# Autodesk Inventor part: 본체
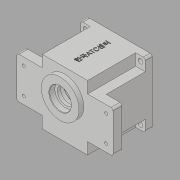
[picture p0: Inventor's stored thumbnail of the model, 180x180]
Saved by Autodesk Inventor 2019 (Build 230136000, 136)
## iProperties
Created: 2020-01
Part Number: 본체
Material: 일반
Document SubType Name: Modeling
Designer: 323-10
Density: 1 g/cm^3
Appearance: 기본값
Mass: 876.342 g
Surface Area: 793.825 cm^2
Volume: 324.571 cm^3
Author: 323-10
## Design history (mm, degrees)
sketch "스케치1"
  geometry: L1 (-47, -47)-(47, -47); L2 (47, -47)-(47, 47); L3 (47, 47)-(-47, 47); L4 (-47, 47)-(-47, -47); L5 (-47, -47)-(47, 47); L6 (47, -47)-(-47, 47); 1 further point
  constraints: 12 end point, 2 midpoint, 2 parallel, 1 horizontal, 1 perpendicular
  dimensions: "d0" = 94 distance of L3.end L2.end; "d1" = 94 distance of L2.end L1.end
extrude "돌출1" new body sketch "스케치1" distance "d2" = 80; taper "d3" = 0 deg
sketch "스케치2"
  geometry: L1 (70, -30)-(-70, -30); L2 (-70, -30)-(-70, 30); L3 (-70, 30)-(70, 30); L4 (70, 30)-(70, -30); L5 (70, -30)-(-70, 30); L6 (-70, -30)-(70, 30); 1 further point
  constraints: 12 end point, 2 midpoint, 2 parallel, 1 horizontal, 1 perpendicular
  dimensions: "d4" = 140 distance of L2.end L3.end; "d5" = 60 distance of L1.end L2.end
extrude "돌출2" join sketch "스케치2" distance "d6" = 13; taper "d7" = 0 deg
sketch "스케치3"
  geometry: C1 r 27.5 at (0, 11); 1 further point
  constraints: 1 centre point, 1 vertical alignment
  dimensions: "d8" = 55 diameter of C1; "d9" = 11 distance of point (0, 0) C1.centre
extrude "돌출3" join sketch "스케치3" distance "d10" = 7; taper "d11" = 0 deg
sketch "스케치4"
  geometry: C1 r 27.5 at (0, 0) reference; C2 r 16 at (0, 0); 1 further point
  constraints: 1 centre point, 1 coincident
  dimensions: "d12" = 32 diameter of C2
extrude "돌출4" cut sketch "스케치4" distance "d13" = 8.3; taper "d14" = 0 deg
sketch "스케치5"
  geometry: C1 r 40 at (0, 0); 1 further point
  constraints: 1 centre point, 1 coincident
  dimensions: "d15" = 80 diameter of C1
extrude "돌출5" cut sketch "스케치5" distance "d16" = 71; taper "d17" = 0 deg
sketch "스케치6"
  geometry: C1 r 21 at (0, 11); C2 r 15 at (0, -20); 1 further point
  constraints: 2 centre point, 2 vertical alignment
  dimensions: "d18" = 11 distance of point (0, 0) C1.centre; "d20" = 20 distance of C2.centre point (0, 0); "d21" = 21 radius of C1; "d22" = 15 radius of C2
extrude "돌출6" join sketch "스케치6" distance "d23" = 7; taper "d24" = 0 deg
sketch "스케치7"
  geometry: C1 r 17.5 at (0, 11); A1 r 21 centre (0, 11) between (8.978, -7.984) and (-8.978, -7.984) reference; 1 further point
  constraints: 1 centre point, 1 coincident
  dimensions: "d25" = 35 diameter of C1
extrude "돌출7" cut sketch "스케치7" distance "d26" = 10; taper "d27" = 0 deg
sketch "스케치8"
  geometry: C1 r 11 at (0, -20); A1 r 15 centre (0, -20) between (-8.978, -7.984) and (8.978, -7.984) reference; 1 further point
  constraints: 1 centre point, 1 coincident
  dimensions: "d28" = 22 diameter of C1
extrude "돌출8" cut sketch "스케치8" distance "d29" = 7; taper "d30" = 0 deg
sketch "스케치9"
  geometry: C1 r 11 at (0, 0) reference; C2 r 9.5 at (0, 0); 1 further point
  constraints: 1 centre point, 1 coincident
  dimensions: "d31" = 19 diameter of C2
extrude "돌출9" cut sketch "스케치9" distance "d32" = 3; taper "d33" = 0 deg
sketch "스케치10"
  geometry: C1 r 16 at (0, 0) reference; C2 r 12.5 at (0, 0); 1 further point
  constraints: 1 centre point, 1 coincident
  dimensions: "d34" = 25 diameter of C2
extrude "돌출10" cut sketch "스케치10" extent not by distance; stored distance "d35" = 3; taper "d36" = 0 deg
sketch "스케치11"
  geometry: C1 r 43 at (0, 0); 1 further point
  constraints: 1 centre point, 1 coincident
  dimensions: "d37" = 86 diameter of C1
extrude "돌출11" cut sketch "스케치11" distance "d38" = 9; taper "d39" = 0 deg
sketch "스케치12" dims "d40" = 36
  geometry: L1 (36, -4)-(39.799, -4); L2 (36, 4)-(39.799, 4); A1 r 4 centre (36, 0) between (36, 4) and (36, -4); A2 r 40 centre (0, 0) between (39.799, -4) and (39.799, 4) reference; A3 r 40 centre (0, 0) between (39.799, -4) and (39.799, 4); A4 r 4 centre (36, 0) between (40, 0) and (36, 4); A5 r 4 centre (36, 0) between (36, -4) and (40, 0); 2 further points
  constraints: 11 point on circle, 4 centre point, 4 end point, 4 tangent, 2 coincident, 2 horizontal, 2 horizontal alignment, 2 other
  dimensions: "d42" = 4 radius of A4
extrude "돌출12" join sketch "스케치12" stored distance "d43" = 9; taper "d44" = 0 deg
fillet "모깎기1" dims "d45" = 3
sketch "스케치13"
  geometry: 2 further points
  dimensions: "d46" = 19 vertical distance of point (0, 0) point (-60, 19); "d47" = 60 horizontal distance of point (0, 0) point (-60, 19)
hole "구멍1" sketch "스케치13" at (-60, 19) diameter "d48" = 4.5; stored, may be unused: countersink angle "d52" = 90 deg, drill point angle "d54" = 118 deg; dims "d49" = 6, "d50" = 10, "d51" = 5, "d53" = 8
sketch "스케치14"
  geometry: L1 (47, 30)-(47, 47) reference; L2 (47, 47)-(33, 47); L3 (33, 47)-(33, 30); L4 (33, 30)-(47, 30); L5 (47, 30)-(47, 47); 1 further point
  constraints: 8 end point, 2 parallel, 1 horizontal, 1 perpendicular
  dimensions: "d55" = 33 distance from line of point (0, 0) L3; "d56" = 30 distance from line of point (0, 0) L4
extrude "돌출13" cut sketch "스케치14" distance "d57" = 70; taper "d58" = 0 deg
sketch "스케치15"
  geometry: C1 r 3.5 at (40, 40); 1 further point
  constraints: 1 centre point
  dimensions: "d59" = 7 diameter of C1; "d60" = 40 horizontal distance of point (0, 0) C1.centre; "d61" = 40 horizontal distance of point (0, 0) C1.centre
extrude "돌출14" cut sketch "스케치15" extent not by distance; stored distance "d62" = 70; taper "d63" = 0 deg
chamfer "모따기1" distance "d64" = 0.8; stored, may be unused: second distance "d65" = 2, angle "d66" = 30 deg
chamfer "모따기2" distance "d67" = 1; stored, may be unused: second distance "d68" = 2, angle "d69" = 45 deg
fillet "모깎기2" dims "d70" = 3
chamfer "모따기3" distance "d71" = 1; stored, may be unused: second distance "d72" = 2, angle "d73" = 45 deg
sketch "스케치16"
  geometry: A1 r 4 centre (36, 0) between (36, 4) and (36, -4) reference; 2 further points
  constraints: 1 coincident
hole "구멍2" sketch "스케치16" at (36, 0) diameter "d74" = 3.242; stored, may be unused: countersink angle "d78" = 90 deg, drill point angle "d80" = 118 deg; dims "d75" = 7, "d76" = 10, "d77" = 5, "d79" = 9
fillet "모깎기3" dims "d81" = 3
sketch "스케치17"
  geometry: L1 (0, 0)-(-66, 0) reference; L2 (-77, 80)-(11, 80) reference; 3 further points
  constraints: 1 midpoint, 1 vertical alignment, 1 other
  dimensions: "d82" = 40 distance from line of L2 point (-33, 40)
feature "엠보싱1" sketch "스케치17" dims "d83" = 0.5, "d84" = 0
node "솔리드1"
mirror "미러1"
mirror "미러2"
mirror "미러3"
mirror "미러4"
mirror "미러5"
mirror "미러6"
mirror "미러7"
mirror "미러8"
node "작업 평면1"
